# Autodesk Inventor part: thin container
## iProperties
Author: Administrator
Created: 2001-03
Part Number: thin container
Document SubType Name: Modeling
Designer: Administrator
Control State: 0
Master: False
Checked Out: False
PropertySet Name: Design Tracking Control
Shininess: 20.0
PropertySet Name: _Private Model Information
Density: 0.0
Volumn: 0.0
Area: 0.0
PropertySet Name: Model Information
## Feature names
1. Extrusion1
